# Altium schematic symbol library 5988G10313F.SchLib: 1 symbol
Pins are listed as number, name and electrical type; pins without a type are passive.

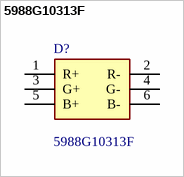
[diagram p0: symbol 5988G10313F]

## 5988G10313F
designator D?
LED, Red, Green, Blue, SMD, 110 , Square, R 20mA, G 20mA, B 20mA; Manufacturer_Name: Dialight; Geometry.Height: 2.577mm
footprint 5988G10313F
pins: 1 R+, 2 R-, 3 G+, 4 G-, 5 B+, 6 B-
